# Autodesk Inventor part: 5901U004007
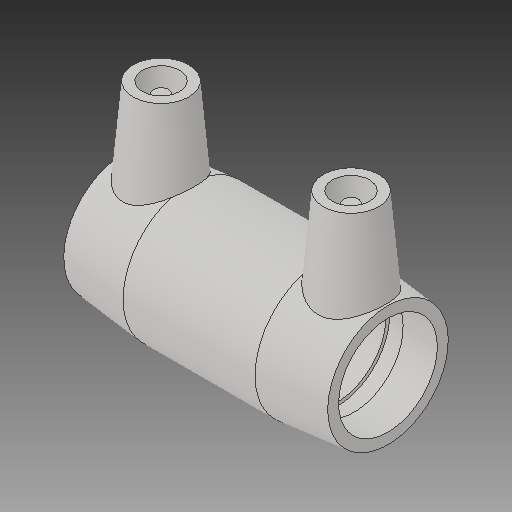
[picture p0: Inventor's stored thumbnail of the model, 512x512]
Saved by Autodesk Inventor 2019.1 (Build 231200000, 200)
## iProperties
Created: 2017-06
Part Number: 5901U004007
Material: Generic
Description: PLASSON CTS COUPLER 3/4''
Document SubType Name: Modeling
Designer: KIM
Mass: 72.9589 g
Surface Area: 285.531 cm^2
Volume: 72.9589 cm^3
Density: 1 g/cm^3
Appearance: Default
Author: KIM
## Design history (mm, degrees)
derived "5901U.ipt"
feature "Solid1::5901U.ipt"
tag "TaggingFeature1"
body "Solid1"
other parameters: "d0" = 71.12, "d1" = 26.6, "d2" = 36.068, "d3" = 34.544, "d4" = 17.78, "d5" = 32.4612, "d6" = 21.28, "d7" = 26.6, "d8" = 168 deg, "d10" = 13.8176, "d11" = 4.60587, "d29" = 38.1, "d30" = 15, "d31" = 25.6032, "d34" = 5 deg, "d41" = 4, "d42" = 14, "d43" = 0, "d48" = 3, "d49" = 0, "d_" = 26.6, "L_" = 71.12, "L_1" = 34.544, "D_" = 36.068, "A_" = 38.1, "d_2" = 12
